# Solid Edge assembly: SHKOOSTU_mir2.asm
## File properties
Author: Türk
Template: Iso Assembly.asm
Last saved by: Türk
Revision: 2
Application: Solid Edge
Username: Türk
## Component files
Shockabsorber.par
ShKolvikoostu.asm
Shkaan.par
Poldikoostu5.asm
Esimene vedru_mir1.par
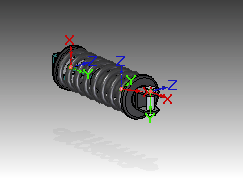
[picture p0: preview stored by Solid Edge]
